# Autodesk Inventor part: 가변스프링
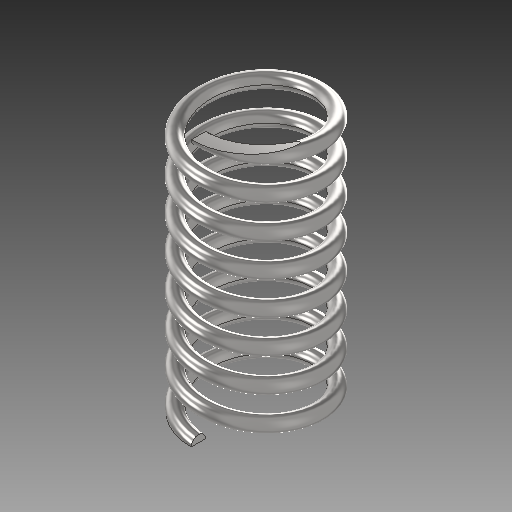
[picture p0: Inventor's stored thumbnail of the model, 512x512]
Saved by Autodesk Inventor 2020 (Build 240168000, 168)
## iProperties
Created: 2021-12
Part Number: 가변스프링
Material: 강철, 탄소
Document SubType Name: Modeling
Designer: MIRAE
Density: 7.85 g/cm^3
Appearance: 반연마
Mass: 9.80168 g
Surface Area: 25.2576 cm^2
Volume: 1.24862 cm^3
Author: MIRAE
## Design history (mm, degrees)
sketch "가변스프링-스케치"
  geometry: L1 (0, 0)-(-8, 0); L2 (-8, 0)-(-8, -37); L3 (-8, -37)-(0, -37); L4 (0, -37)-(0, 0); C1 r 1 at (-8, 0)
  constraints: 8 end point, 2 parallel, 1 centre point, 1 coincident, 1 horizontal, 1 perpendicular, 1 vertical alignment
  dimensions: "d2" = 16 diameter of L2 L4; "d3" = 2 diameter of C1
feature "가변스프링" sketch "가변스프링-스케치" pitch "d4" = 10; turns "d6" = 8; dims "d5" = 37 (derived), "d7" = 0, angle "d8" = 90 deg, angle "d9" = 90 deg, "d10" = 0, "d11" = 0
node "작업 평면1"
feature "분할1"
feature "분할2"
node "솔리드1"
other parameters: "d12" = -37 (derived)
